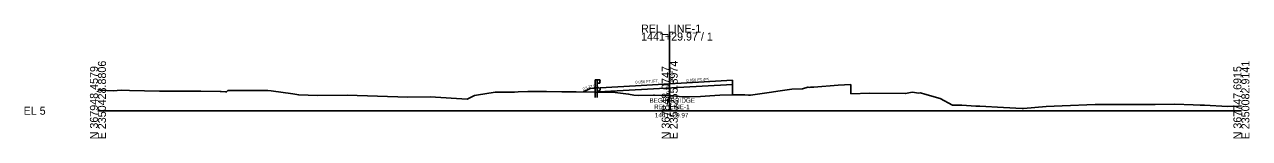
# Model space of a CAD drawing. Extents: x -26 to 2803, y -10 to 9522.
# Drawn here: x -25.7 to 402.8, y 4990.3 to 5030.1 of the extents above; entities that cross this region are included whole.
import ezdxf

# ---------------------------------------------------------------- set-up
doc = ezdxf.new("R2010")
doc.units = 0
for name, color, linetype in [('RD_GPK_XS_Cell', 7, 'Continuous'), ('RD_PD_MedBWall', 7, 'Continuous'), ('RD_PD_PatLn_526', 7, 'Continuous'), ('RD_PD_SuperShp_WB_526', 7, 'Continuous'), ('RD_XS_ExGround', 7, 'Continuous'), ('RD_XS_GR', 7, 'Continuous'), ('RD_XS_Pave', 7, 'Continuous'), ('RD_XS_PaveOvlay', 7, 'Continuous'), ('RD_XS_PaveShd', 7, 'Continuous'), ('RD_XS_TieSlope', 7, 'Continuous'), ('RD_XS_TX_Elev_EX', 7, 'Continuous'), ('RD_XS_TX_Elev_PR', 7, 'Continuous'), ('RD_XS_TX_Slope', 7, 'Continuous')]:
    doc.layers.add(name, color=color, linetype=linetype)

msp = doc.modelspace()

# ---------------------------------------------------------------- linework, layer by layer
at = {"layer": 'RD_GPK_XS_Cell'}
for p, q in [((200, 5000), (200, 5027.32)), ((0, 5000), (200, 5000)), ((200, 5000), (400, 5000))]:
    msp.add_line(p, q, dxfattribs=at)
at = {"layer": 'RD_PD_MedBWall'}
msp.add_line((222.02, 5010.63), (222.02, 5005.51), dxfattribs=at)
at = {"layer": 'RD_XS_ExGround'}
msp.add_lwpolyline([(0, 5007.27), (0.8, 5007.17), (5.35, 5006.91), (8.14, 5007.24), (11.02, 5007.12), (21.51, 5006.84), (25.38, 5006.81), (32.92, 5006.82), (36, 5006.83), (42.73, 5006.69), (43.1, 5006.67), (44.66, 5006.59), (44.98, 5006.58), (45.47, 5007.08), (46.7, 5007.09), (49.57, 5007.09), (53.58, 5007.02), (59.45, 5007.09), (60.6, 5006.93), (68.22, 5005.88), (70.25, 5005.5), (76.79, 5005.33), (87.23, 5005.4), (108.43, 5004.71), (116.19, 5004.83), (129.11, 5004.09), (131.76, 5005.33), (132.46, 5005.47), (138.92, 5006.47), (144.48, 5006.48), (145.77, 5006.53), (146.95, 5006.56), (150.33, 5006.73), (156.93, 5006.72), (162.31, 5006.65), (164.76, 5006.61), (167.28, 5006.62), (173.92, 5006.5), (180.94, 5006.39), (185.6, 5005.8), (187.44, 5005.45), (189.05, 5005.38), (194.32, 5005.48), (194.69, 5005.45), (200, 5005.21), (201.08, 5005.16), (204.37, 5004.83), (206.96, 5004.83), (210.76, 5004.97), (214.01, 5005.21), (217.6, 5005.48), (221.87, 5005.51), (226.35, 5005.51), (227.55, 5005.44), (228.28, 5005.49), (234.76, 5006.35), (238.62, 5006.9), (242.78, 5007.58), (246.5, 5007.67), (248.37, 5008.24), (248.8, 5008.15), (249.21, 5008.18), (250.45, 5008.27), (258.98, 5008.91), (263.36, 5009.11), (263.38, 5005.93), (270, 5006.15), (282.53, 5005.99), (284.82, 5006.43), (287.19, 5006.18), (287.8, 5006.24), (289.27, 5005.84), (294.6, 5004.23), (298.99, 5001.9), (302.16, 5001.89), (307.07, 5001.65), (308.48, 5001.54), (316.73, 5001.1), (323.37, 5000.75), (323.79, 5000.73), (331.73, 5001.43), (337.35, 5001.7), (348.81, 5002.18), (354.21, 5002.22), (356.45, 5002.23), (368.42, 5002.19), (369.02, 5002.18), (369.79, 5002.2), (376.72, 5002.31), (383.19, 5002.02), (385.57, 5001.91), (387.04, 5001.96), (395.13, 5001.53), (399.02, 5001.61), (400, 5001.74)], dxfattribs=at)
at = {"layer": 'RD_XS_GR'}
msp.add_line((172.24, 5007.76), (169.86, 5006.57), dxfattribs=at)
at = {"layer": 'RD_XS_Pave'}
for p, q in [((212.02, 5010.07), (222.02, 5010.63)), ((188, 5008.73), (175.7, 5008.04))]:
    msp.add_line(p, q, dxfattribs=at)
at = {"layer": 'RD_XS_PaveOvlay'}
for p, q in [((222.02, 5009.22), (175.2, 5006.6)), ((175.2, 5007.1), (175.7, 5007.13)), ((175.2, 5007.1), (175.2, 5006.6)), ((175.7, 5008.04), (175.7, 5007.13))]:
    msp.add_line(p, q, dxfattribs=at)
at = {"layer": 'RD_XS_PaveShd'}
for p, q in [((200, 5009.4), (212.02, 5010.07)), ((188, 5008.73), (200, 5009.4))]:
    msp.add_line(p, q, dxfattribs=at)
at = {"layer": 'RD_XS_TieSlope'}
for p, q in [((174.61, 5010.84), (173.95, 5010.84)), ((173.95, 5010.84), (173.95, 5008.05)), ((175.53, 5010.84), (174.61, 5010.84)), ((174.61, 5010.84), (174.61, 5008.1)), ((175.53, 5009.68), (174.61, 5009.68)), ((175.53, 5009.68), (175.53, 5010.84)), ((175.53, 5010.77), (175.7, 5010.57)), ((175.7, 5010.52), (175.53, 5010.32)), ((175.7, 5010), (175.53, 5010.2)), ((175.53, 5009.75), (175.7, 5009.95)), ((175.7, 5010.57), (175.7, 5010.52)), ((175.7, 5009.95), (175.7, 5010)), ((173.95, 5008.05), (173.95, 5004.63)), ((174.61, 5004.63), (174.61, 5008.1))]:
    msp.add_line(p, q, dxfattribs=at)
at = {"layer": 'RD_XS_TX_Slope'}
msp.add_line((175.7, 5008.04), (172.24, 5007.76), dxfattribs=at)

# ---------------------------------------------------------------- texts
at = {"layer": 'RD_GPK_XS_Cell'}
for s, p in [('1441+29.97 / 1', (190, 5024.52)), ('REL_LINE-1', (190, 5027.32)), ('EL 5', (-26, 4998.6))]:
    msp.add_text(s, height=2.8, dxfattribs=at).set_placement(p)
for s, p in [('N 367948.4579', (0, 4990)), ('E 2350428.8806', (2.8, 4990)), ('N 367848.0747', (200, 4990)), ('E 2350255.8974', (202.8, 4990)), ('N 367747.6915', (400, 4990)), ('E 2350082.9141', (402.8, 4990))]:
    msp.add_text(s, height=2.8, rotation=90, dxfattribs=at).set_placement(p)
at = {"layer": 'RD_PD_PatLn_526'}
for s, p in [('BEGIN BRIDGE', (192.92, 5002.78)), ('REL_LINE-1', (194.56, 5000.54)), ('1441+29.97', (194.82, 4997.64))]:
    msp.add_text(s, height=1.6, dxfattribs=at).set_placement(p)
at = {"layer": 'RD_PD_SuperShp_WB_526'}
msp.add_text(' 14.40', height=1.2, rotation=90, dxfattribs=at).set_placement((201.2, 5009.4))
at = {"layer": 'RD_XS_TX_Elev_EX'}
msp.add_text('10.21', height=1, rotation=90, dxfattribs=at).set_placement((199.81, 5005.21))
at = {"layer": 'RD_XS_TX_Elev_PR'}
for s, rotation, p in [('0.056 FT./FT.', 3.2052, (188, 5009.47)), ('0.056 FT./FT.', 3.2052, (205.89, 5010.06)), ('2:1', 26.5651, (169.83, 5006.95)), ('12.5:1', 4.5739, (171.49, 5007.9))]:
    msp.add_text(s, height=1, rotation=rotation, dxfattribs=at).set_placement(p)

doc.saveas('drawing.dxf')
